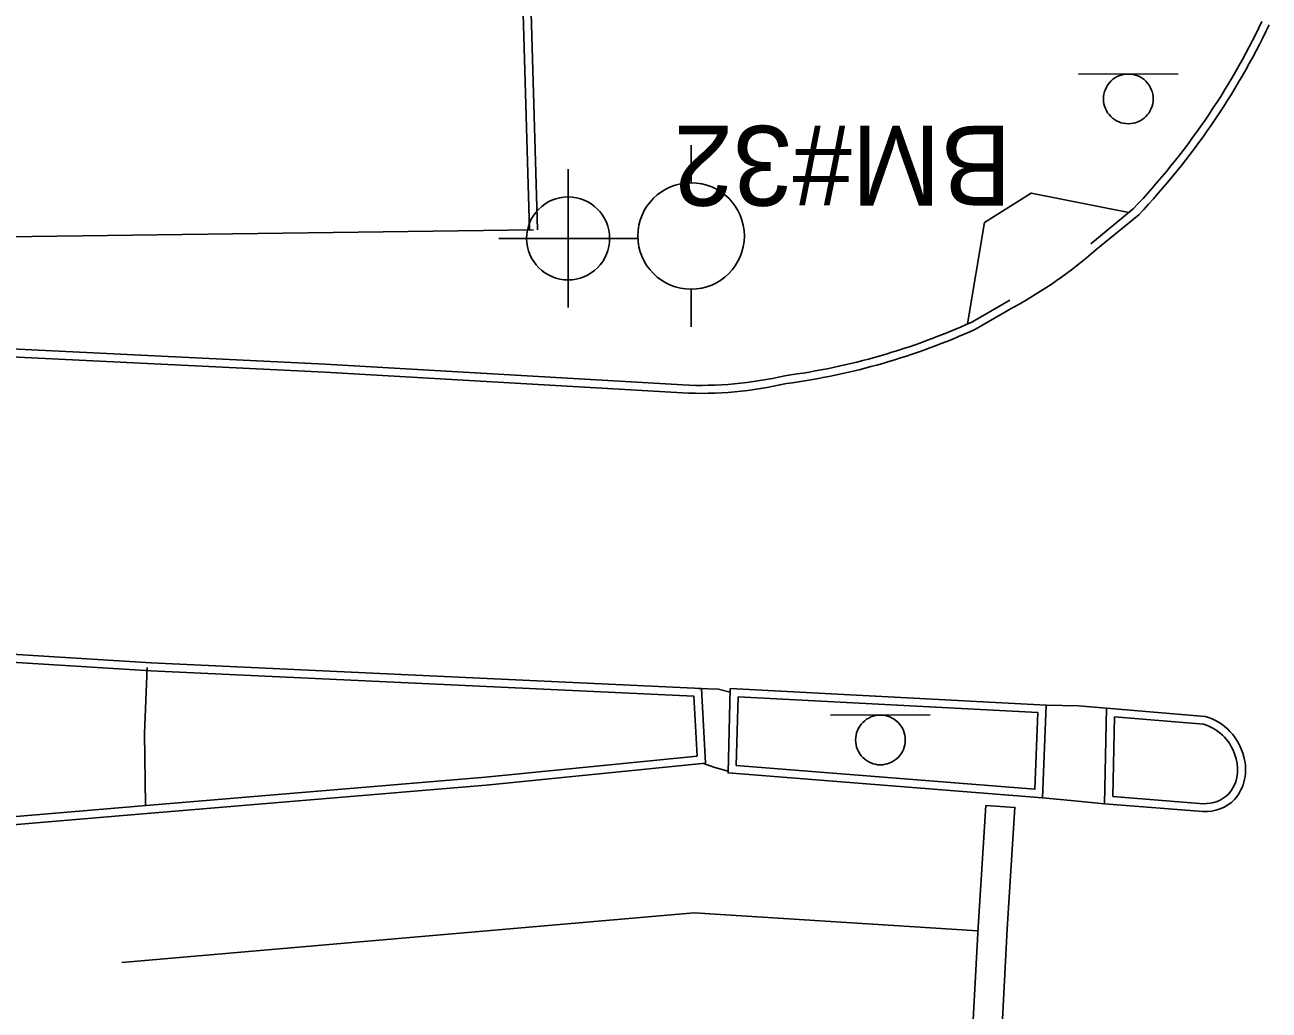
# Model space of a CAD drawing. Extents: x 2145380 to 2156929, y 139568 to 149130.
# Drawn here: x 2150576.6 to 2150670, y 140325.9 to 140400 of the extents above; entities that cross this region are included whole.
import ezdxf

# ---------------------------------------------------------------- set-up
doc = ezdxf.new("R2010")
doc.units = 0
for name, color, linetype in [('SURV_Benchmark', 7, 'Continuous'), ('SURV_Text', 7, 'Continuous'), ('TOPO_Asphalt', 7, 'Continuous'), ('TOPO_Concrete', 7, 'Continuous'), ('TOPO_Curb Back', 7, 'Continuous'), ('TOPO_Misc Line', 7, 'Continuous'), ('TOPO_Power Pole', 7, 'Continuous'), ('TOPO_Sidewalk', 7, 'Continuous'), ('TOPO_Sign', 7, 'Continuous'), ('TOPO_Wall Freestanding', 7, 'Continuous')]:
    doc.layers.add(name, color=color, linetype=linetype)

# ---------------------------------------------------------------- blocks, each defined once
blk = doc.blocks.new('POWPOL')
at = {"layer": 'TOPO_Power Pole'}
for p, q in [((0, 10.16), (0, 17.34)), ((0, -10.16), (0, -17.34))]:
    blk.add_line(p, q, dxfattribs=at)
blk.add_circle((0, 0), 10.16, dxfattribs=at)
blk = doc.blocks.new('BM')
at = {"layer": 'SURV_Benchmark'}
for p, q in [((0, 2.493), (0, 4.153)), ((-2.493, 0), (-4.157, 0)), ((4.157, 0), (2.493, 0)), ((0, -4.157), (0, -2.493))]:
    blk.add_line(p, q, dxfattribs=at)
for points in [[(-0.002, 2.495), (0, 2.493), (0, 0), (2.493, 0), (2.493, 0), (2.494, 0.002)], [(-0.002, 2.495), (0, 2.493), (0, 0), (2.493, 0), (2.493, 0), (2.494, 0.002), (2.494, 0.002)], [(-2.496, -0.001), (-2.493, 0), (0, 0), (0, -2.493), (0.001, -2.495)], [(-2.496, -0.001), (-2.493, 0), (0, 0), (0, -2.493), (0.001, -2.495)]]:
    blk.add_lwpolyline(points, dxfattribs=at)
for centre, start, end in [((0.001, -0.001), 90.06381, 180.00681), ((-0.002, -0.001), 0.06381, 90.00681), ((-0.002, -0.001), 0.06381, 90.00681), ((0.001, 0.001), 180.06381, 270.00681), ((0.001, 0.001), 180.06381, 270.00681), ((0.001, -0.001), 269.94719, 359.99266)]:
    blk.add_arc(centre, 2.496, start, end, dxfattribs=at)

msp = doc.modelspace()

# ---------------------------------------------------------------- linework, layer by layer
at = {"layer": 'TOPO_Asphalt'}
for points in [[(2150629.561, 140349.832), (2150628.671, 140350.041), (2150627.148, 140350.107)], [(2150657.834, 140348.609), (2150655.725, 140348.803), (2150653.307, 140348.854)], [(2150627.558, 140344.462), (2150628.393, 140344.169), (2150629.404, 140343.887)], [(2150653.032, 140341.875), (2150655.675, 140341.637), (2150657.685, 140341.432)]]:
    msp.add_lwpolyline(points, dxfattribs=at)
msp.add_arc((2150633.916, 140409.595), 35.196, 298.77424, 311.03755, dxfattribs=at)
at = {"layer": 'TOPO_Concrete'}
msp.add_lwpolyline([(2150585.628, 140341.349), (2150585.557, 140346.725), (2150585.764, 140351.662)], dxfattribs=at)
at = {"layer": 'TOPO_Curb Back'}
for p, q in [((2150657.685, 140341.419), (2150657.834, 140348.609)), ((2150657.834, 140348.609), (2150665.236, 140348.001)), ((2150658.297, 140341.973), (2150658.421, 140347.959)), ((2150658.421, 140347.959), (2150665.127, 140347.408)), ((2150665.113, 140341.439), (2150658.297, 140341.973)), ((2150665.077, 140340.84), (2150657.685, 140341.419))]:
    msp.add_line(p, q, dxfattribs=at)
for points in [[(2150614.484, 140384.546), (2150613.81, 140407.683), (2150613.552, 140424.381), (2150619.75, 140430.443), (2150623.971, 140434.567), (2150651.986, 140434.691), (2150660.871, 140434.774), (2150662.285, 140462.069), (2150662.492, 140466.545), (2150668.346, 140465.11)], [(2150615.083, 140384.563), (2150614.41, 140407.696), (2150614.156, 140424.132), (2150620.169, 140430.013), (2150624.217, 140433.968), (2150651.99, 140434.091), (2150661.441, 140434.179), (2150662.884, 140462.04), (2150663.058, 140465.788), (2150668.176, 140464.534)], [(2150659.845, 140386.139), (2150656.643, 140383.511)], [(2150660.255, 140385.699), (2150657.024, 140383.047)], [(2150626, 140372.904), (2150599.124, 140374.474), (2150554.01, 140376.663), (2150525.349, 140378.14), (2150513.464, 140378.532)], [(2150650.559, 140379.265), (2150647.706, 140377.628)], [(2150650.857, 140378.745), (2150647.98, 140377.093)], [(2150625.969, 140372.305), (2150599.092, 140373.874), (2150553.98, 140376.064), (2150525.323, 140377.54), (2150513.437, 140377.933)], [(2150536.501, 140354.608), (2150559.837, 140353.658), (2150586.057, 140352.022), (2150627.395, 140350.096), (2150627.699, 140344.476), (2150611.223, 140342.826), (2150585.733, 140340.709), (2150559.948, 140338.526)], [(2150536.47, 140354.009), (2150559.806, 140353.058), (2150586.025, 140351.423), (2150626.825, 140349.521), (2150627.069, 140345.016), (2150611.168, 140343.424), (2150585.683, 140341.306), (2150559.876, 140339.122)], [(2150629.568, 140350.097), (2150653.307, 140348.854), (2150653.032, 140341.875), (2150629.4, 140343.758), (2150629.568, 140350.097)], [(2150630.151, 140349.465), (2150652.685, 140348.285), (2150652.457, 140342.523), (2150630.015, 140344.311), (2150630.151, 140349.465)]]:
    msp.add_lwpolyline(points, dxfattribs=at)
for centre, radius, start, end in [((2150620.149, 140423.734), 54.674, 316.55729, 334.53733), ((2150620.146, 140423.736), 55.276, 316.51838, 334.52885), ((2150627.02, 140423.227), 50.072, 277.63486, 294.40087), ((2150627.021, 140423.224), 50.669, 277.66652, 294.43387), ((2150627.317, 140401.071), 28.797, 267.31591, 282.96959), ((2150627.317, 140401.069), 28.195, 267.32264, 283.0268), ((2150664.117, 140344.021), 4.134, 13.07416, 74.28257), ((2150664.117, 140344.021), 3.534, 12.7596, 73.38082), ((2150664.895, 140343.979), 2.792, 319.61972, 17.13853), ((2150664.895, 140343.979), 3.392, 319.13547, 16.74589), ((2150665.214, 140344.034), 2.596, 267.76568, 314.13324), ((2150665.214, 140344.033), 3.196, 267.53968, 314.65651)]:
    msp.add_arc(centre, radius, start, end, dxfattribs=at)
at = {"layer": 'TOPO_Misc Line'}
msp.add_lwpolyline([(2150648.768, 140341.297), (2150650.949, 140341.159), (2150650.369, 140332.026), (2150649.809, 140321.374), (2150647.626, 140321.488), (2150648.187, 140332.153)], close=True, dxfattribs=at)
msp.add_lwpolyline([(2150648.173, 140331.886), (2150626.864, 140333.24), (2150583.863, 140329.509)], dxfattribs=at)
at = {"layer": 'TOPO_Sidewalk'}
msp.add_lwpolyline([(2150659.515, 140385.868), (2150652.184, 140387.326), (2150648.668, 140385.103), (2150647.396, 140377.489)], dxfattribs=at)
at = {"layer": 'TOPO_Sign'}
for points in [[(2150655.722, 140396.27), (2150663.215, 140396.277)], [(2150659.472, 140396.27), (2150659.472, 140396.27)], [(2150657.604, 140394.402), (2150657.604, 140394.402)], [(2150661.339, 140394.402), (2150661.339, 140394.402)], [(2150659.472, 140392.534), (2150659.472, 140392.534)], [(2150637.097, 140348.099), (2150644.591, 140348.105)], [(2150640.847, 140348.098), (2150640.847, 140348.098)], [(2150638.98, 140346.23), (2150638.98, 140346.23)], [(2150642.715, 140346.23), (2150642.715, 140346.23)], [(2150640.847, 140344.363), (2150640.847, 140344.363)]]:
    msp.add_lwpolyline(points, dxfattribs=at)
for centre, start, end in [((2150659.472, 140394.402), 89.99996, 180.00004), ((2150659.472, 140394.402), 359.99996, 90.00004), ((2150659.472, 140394.402), 179.99996, 270.00004), ((2150659.472, 140394.402), 269.99996, 0.00004), ((2150640.847, 140346.23), 89.99996, 180.00004), ((2150640.847, 140346.23), 359.99996, 90.00004), ((2150640.847, 140346.23), 179.99996, 270.00004), ((2150640.847, 140346.23), 269.99996, 0.00004)]:
    msp.add_arc(centre, 1.868, start, end, dxfattribs=at)
at = {"layer": 'TOPO_Wall Freestanding'}
msp.add_lwpolyline([(2150515.169, 140383.2), (2150563.916, 140383.895), (2150614.784, 140384.555)], dxfattribs=at)

# ---------------------------------------------------------------- block references
at = {"layer": 'SURV_Benchmark', "xscale": 1.25, "yscale": 1.25}
msp.add_blockref('BM', (2150617.382, 140383.919), dxfattribs=at)
at = {"layer": 'TOPO_Power Pole', "xscale": 0.39370000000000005, "yscale": 0.3937000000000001}
msp.add_blockref('POWPOL', (2150626.624, 140384.102), dxfattribs=at)

# ---------------------------------------------------------------- texts
at = {"layer": 'SURV_Text'}
msp.add_text('BM#32', height=6, rotation=180, dxfattribs=at).set_placement((2150650.726, 140392.378))

doc.saveas('drawing.dxf')
